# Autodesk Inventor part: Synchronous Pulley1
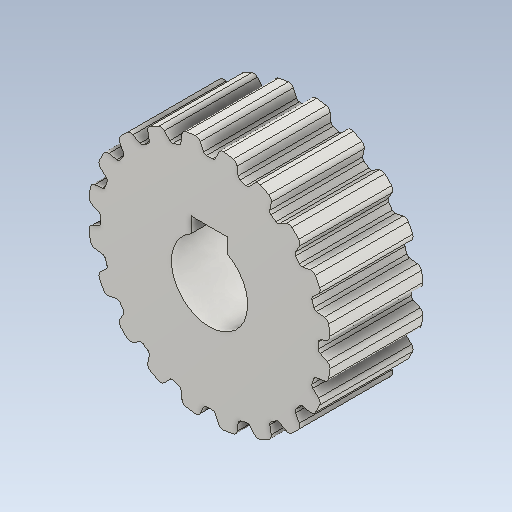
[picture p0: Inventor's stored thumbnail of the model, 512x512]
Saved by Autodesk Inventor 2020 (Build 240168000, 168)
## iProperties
CustomPartVersion: 1
Created: 2019-09
Part Number: Synchronous Pulley1
Material: Steel
Document SubType Name: Modeling
Designer: user
Density: 7.85 g/cm^3
Appearance: Steel
Mass: 61.3214 g
Surface Area: 33.376 cm^2
Volume: 7.81165 cm^3
Author: user
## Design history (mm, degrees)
sketch "Pulley Sketch"
  geometry: L1 (-1.401, 15.854)-(-0.66, 14.265); L2 (-0.66, 14.265)-(0.66, 14.265); L3 (0.66, 14.265)-(1.401, 15.854); L4 (0, 0)-(0, 15.916); C1 r 16.17 at (0, 0); A1 r 15.916 centre (0, 0) between (-1.401, 15.854) and (1.401, 15.854); 2 further points
  constraints: 8 end point, 3 coincident, 3 point on circle, 2 centre point, 1 horizontal, 1 midpoint, 1 point on line, 1 vertical, 1 vertical alignment, 3 other
  dimensions: "d0" = 32.34028 diameter of C1 (computed from da_pb, da_z); "d1" = 0.254 radial gap between concentric circles of C1 A1 (= da_a); "d2" = 1.651 dimension on A1 (= da_hg); "d3" = 50 deg angle of L3 L1 (= 2 x da_fi); "d4" = 1.3208 distance of L1.end L2.end (= da_bw)
extrude "Base Body" new body sketch "Pulley Sketch" stored distance "d5" = 12.192 (= da_bf); taper "d6" = 0 deg
extrude "Tooth" cut sketch "Pulley Sketch" extent not by distance; stored distance "d7" = 12.192 (= da_bf); taper "d8" = 0 deg
fillet "Tooth Fillet" dims "d9" = 0.4064 (= da_rb), "d10" = 0.635 (= da_rt)
feature "Left flange"
feature "Right flange"
sketch "Sketch2"
  geometry: L1 (-2.416, 6.387)-(2.416, 6.387); L2 (2.416, 6.387)-(2.416, 4.378); L3 (-2.416, 4.378)-(-2.416, 6.387); A1 r 5 centre (0, 0) between (-2.416, 4.378) and (2.416, 4.378); 2 further points
  constraints: 6 end point, 2 point on circle, 1 centre point, 1 coincident, 1 horizontal, 1 midpoint, 1 parallel, 1 perpendicular, 1 vertical alignment
  dimensions: "d17" = 10 diameter of A1
extrude "Extrusion3" cut sketch "Sketch2" extent not by distance; stored distance "d18" = 0; taper "d19" = 0 deg
body "Solid1"
pattern_circular "Teeth" dims angle "d12" = 360 deg
other parameters: "da_pb" = 5.08 [user parameter; used in 1 equation term], "da_fi" = 25 deg [user parameter; used in 1 equation term], "da_hg" = 1.651 [user parameter; used in 1 equation term], "da_bw" = 1.3208 [user parameter; used in 1 equation term], "da_rb" = 0.4064 [user parameter; used in 1 equation term], "da_rt" = 0.635 [user parameter; used in 1 equation term], "da_a" = 0.254 [user parameter; used in 3 equation terms], "da_bf" = 12.192 [user parameter; used in 2 equation terms], "d15" = 0, "da_wf" = 1.5 [user parameter; used in 2 equation terms], "da_hf" = 1.5 [user parameter; used in 2 equation terms], "d16" = 0
